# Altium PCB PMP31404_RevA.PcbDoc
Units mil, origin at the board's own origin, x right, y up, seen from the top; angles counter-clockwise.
Board outline 1387.8 x 708.66 mil, 4 copper layers (Top Layer, Layer 1, Layer 2, Bottom Layer), stack 78.58 mil thick; 42 components, 29 nets, 108 pads, 48 vias.
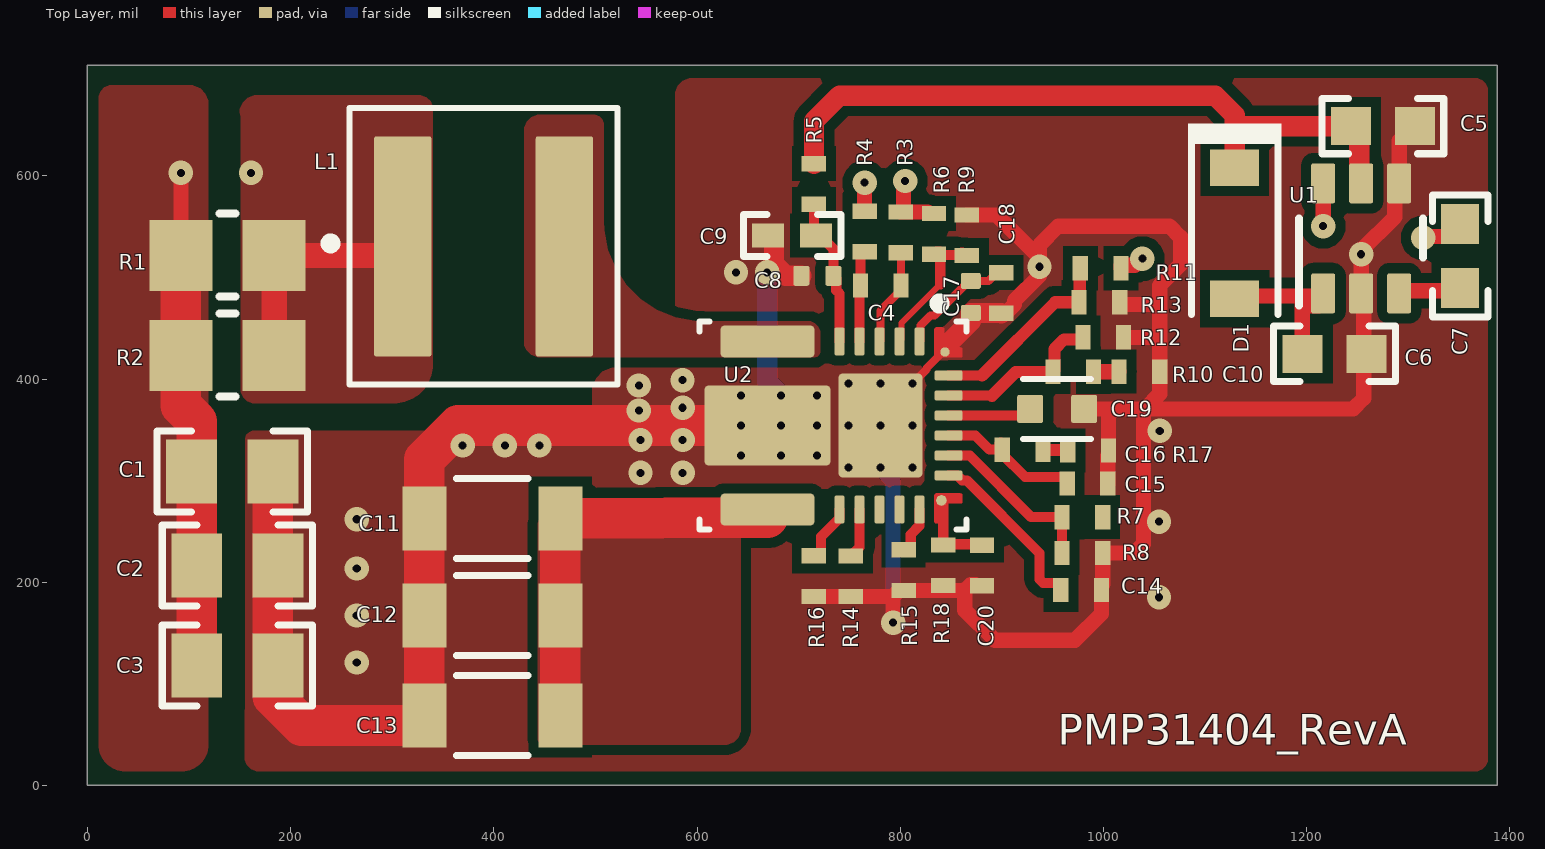
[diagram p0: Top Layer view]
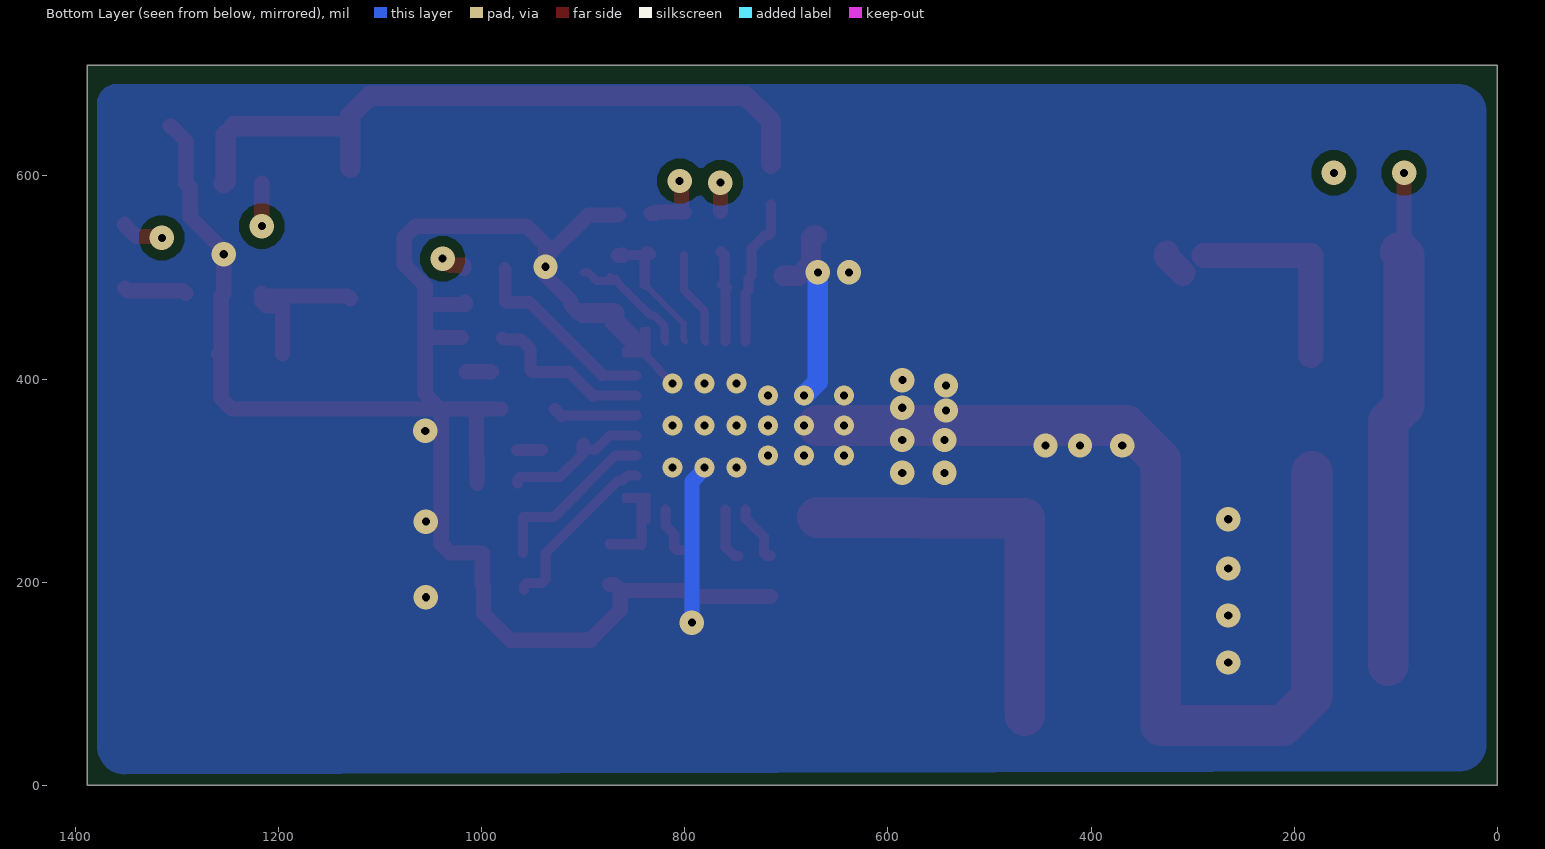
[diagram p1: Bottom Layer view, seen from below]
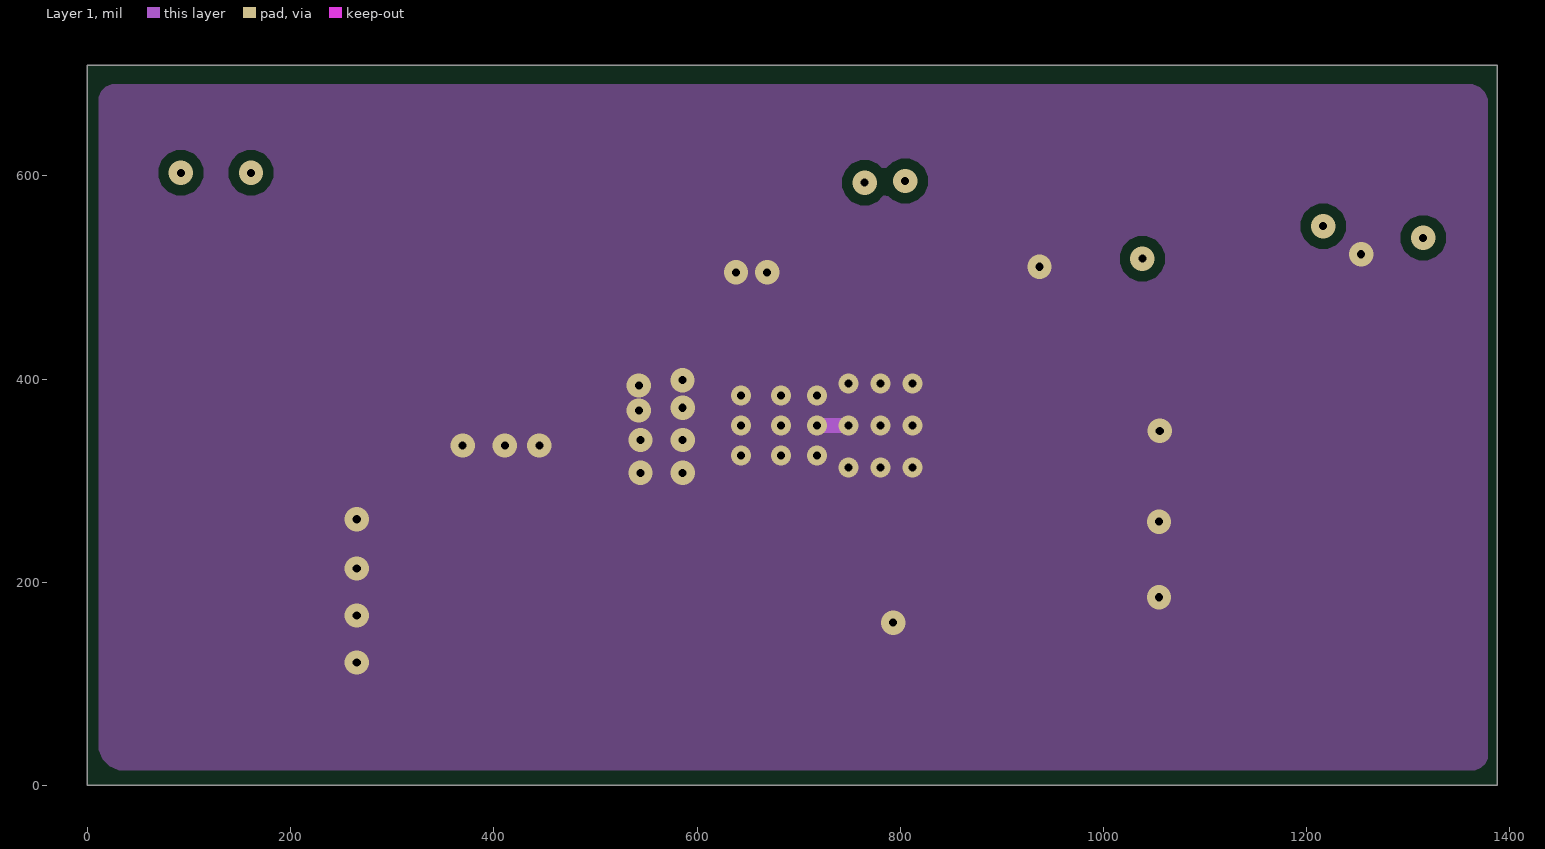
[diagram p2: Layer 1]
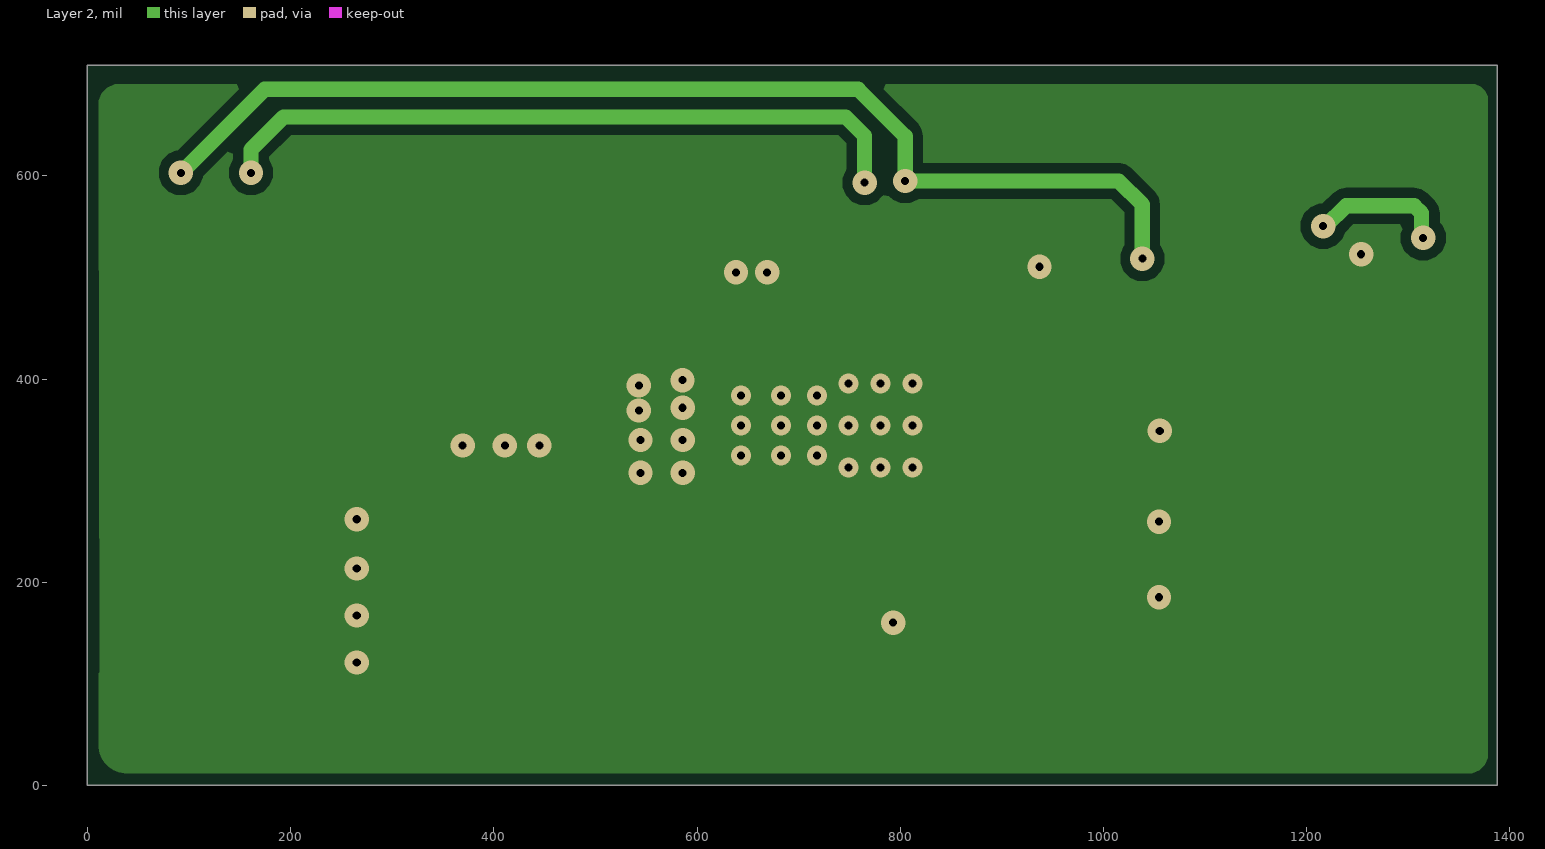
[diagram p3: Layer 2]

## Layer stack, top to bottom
Top Solder: solder mask 0.4, Solder Resist, Dk 3.5
Top Layer: signal copper 4.1339
Dielectric 1: prepreg 2.8, PP-006, Dk 4.1
Layer 1: signal copper 2.756
Dielectric1: core 59.2, FR-4 High Tg, Dk 4.8
Layer 2: signal copper 2.756
Dielectric 2: prepreg 2.8, PP-006, Dk 4.1
Bottom Layer: signal copper 4.1339
Bottom Solder: solder mask 0.4, Solder Resist, Dk 3.5

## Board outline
0,0 0,708.66 1387.8,708.66 1387.8,0

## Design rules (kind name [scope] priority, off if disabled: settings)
AcuteAngle [All] p1: minimum=4.50000000000000E+0001 checktracksonly=FALSE
AssemblyTestPointUsage [All] p1: valid=2
BoardOutlineClearance BoardOutlineClearance_MountingHoles [OnCopper and InComponentClass('Mounting Holes')] p1: gap=1 ignorepadtopadclearanceinfootprint=FALSE
BoardOutlineClearance BoardOutlineClearance_Poly [OnCopper and IsPoly] p2: gap=1 ignorepadtopadclearanceinfootprint=FALSE
BoardOutlineClearance [OnCopper and Not InComponentClass('Logo') and not InComponentClass('FiducialMark') and not InRegion(1000,500,4000,800) and not InPoly] p3: gap=1 ignorepadtopadclearanceinfootprint=FALSE
Clearance Clearance_Keepouts [((IsTrack Or IsArc) And Not InPoly) And IsFree and IsKeepOut vs ((IsTrack Or IsArc) And Not InPoly) And IsFree and IsKeepOut] p1: gap=0 ignorepadtopadclearanceinfootprint=FALSE
Clearance Clearance_Poly [InPolygon] p2: gap=10 ignorepadtopadclearanceinfootprint=TRUE
Clearance Clearance_FiducialMark [IsKeepOut and InComponentClass('FiducialMark') vs IsPad and InComponentClass('FiducialMark')] p3: gap=0 ignorepadtopadclearanceinfootprint=FALSE
Clearance [All] p4: gap=4 ignorepadtopadclearanceinfootprint=TRUE
ComponentClearance ComponentClearance_MountingHoles_FiducialMarks [InComponentClass('Mounting Holes') vs InComponentClass('FiducialMark')] p1: gap=50 collisioncheckmode=3 verticalgap=10 showdistances=FALSE
ComponentClearance ComponentClearance_Shunt [InComponentClass('Header') vs InComponentClass('Shunt')] p2: gap=0 collisioncheckmode=3 verticalgap=0 showdistances=FALSE
ComponentClearance ComponentClearance_Logo [InComponentClass('Logo')] p3: gap=30 collisioncheckmode=3 verticalgap=10 showdistances=FALSE
ComponentClearance ComponentClearance_ScrewToNut [(HasFootprint('NY PMS 440 0025 PH')) vs (HasFootprint('Keystone_1902C'))] p4: gap=5 collisioncheckmode=3 verticalgap=10 showdistances=FALSE
ComponentClearance ComponentClearance_MountingHoles [InComponentClass('Mounting Holes')] p5: gap=100 collisioncheckmode=3 verticalgap=100000 showdistances=FALSE
ComponentClearance ComponentClearance_SmallPassives [HasFootprint('0201*') or HasFootprint('0402*') or HasFootprint('0508') or HasFootprint('0603*') or HasFootprint('0612') or HasFootprint('0805*') or HasFootprint('0815*') or HasFootprint('0830*') or HasFootprint('1206*') or HasFootprint('1210*') or HasFootprint('1808*') or HasFootprint('1812*') or HasFootprint('1825*') or HasFootprint('2010*') or HasFootprint('2220*') or HasFootprint('2225*') or HasFootprint('2512*') or HasFootprint('2728*') or HasFootprint('3518*') vs HasFootprint('0201*') or HasFootprint('0402*') or HasFootprint('0508') or HasFootprint('0603*') or HasFootprint('0612') or HasFootprint('0805*') or HasFootprint('0815*') or HasFootprint('0830*') or HasFootprint('1206*') or HasFootprint('1210*') or HasFootprint('1808*') or HasFootprint('1812*') or HasFootprint('1825*') or HasFootprint('2010*') or HasFootprint('2220*') or HasFootprint('2225*') or HasFootprint('2512*') or HasFootprint('2728*') or HasFootprint('3518*')] p6: gap=5 collisioncheckmode=3 verticalgap=5 showdistances=FALSE
ComponentClearance ComponentClearance_THtoSMT [IsThruComponent vs IsSMTComponent] p7: gap=30 collisioncheckmode=3 verticalgap=30 showdistances=FALSE
ComponentClearance ComponentClearance_THtoTH [IsThruComponent vs IsThruComponent] p8: gap=20 collisioncheckmode=3 verticalgap=30 showdistances=FALSE
ComponentClearance [All] p9: gap=5 collisioncheckmode=3 verticalgap=5 showdistances=FALSE
DiffPairsRouting [All] p1: maxlimit=100 minlimit=10 mostfreqgap=10 toplayer_minwidth=15 toplayer_maxwidth=15 toplayer_prefwidth=15 midlayer1_minwidth=15 midlayer1_maxwidth=15 midlayer1_prefwidth=15 midlayer2_minwidth=15 midlayer2_maxwidth=15 midlayer2_prefwidth=15 bottomlayer_minwidth=15 bottomlayer_maxwidth=15 bottomlayer_prefwidth=15 maxuncoupledlength=1000
FabricationTestPointUsage TestPointUsage [All] p1: valid=2 allowmultiple=FALSE
FabricationTestpoint Testpoint [All] p1: side=3 testpointundercomponent=TRUE minsize=40 maxsize=100 preferedsize=60 minholesize=0 maxholesize=40 preferedholesize=32 testpointgrid=1 allowsidetop=TRUE allowsidebottom=TRUE usegrid=TRUE gridtolerance=0.01
FanoutControl Fanout_LCC [IsLCC] p1: bgadir=Out bgaviamode=Centered fanoutstyle=Auto fanoutdirection=Alternating viagrid=1 // Fanout_LCC (Default Rule)
FanoutControl Fanout_BGA [IsBGA] p2: bgadir=Out bgaviamode=Centered fanoutstyle=Auto fanoutdirection=Alternating viagrid=1 // Fanout_BGA (Default Rule)
FanoutControl Fanout_Default [All] p4: bgadir=Out bgaviamode=Centered fanoutstyle=Auto fanoutdirection=Alternating viagrid=1 // Fanout_Default (Default Rule)
FanoutControl Fanout_Small [(CompPinCount < 5)] p5: bgadir=Out bgaviamode=Centered fanoutstyle=Auto fanoutdirection=OutThenIn viagrid=1 // Fanout_Small (Default Rule)
HoleSize [All] p1: absolutevalues=TRUE maxlimit=251 minlimit=7.87 maxpercent=80.000 minpercent=20.000
MinimumAnnularRing MinimumAnnularRing_ThermalPadVias [IsVia and InAnyComponent] p1: minimumring=5.91
MinimumAnnularRing [All] p2: minimumring=7.87
MinimumSolderMaskSliver MinimumSolderMaskSliver_Logo [InComponentClass('Logo') vs InComponentClass('Logo')] p1: minsoldermaskwidth=0.7
MinimumSolderMaskSliver [All] p2: minsoldermaskwidth=3.94
PlaneConnect [All] p1: planeconnectstyle=Relief reliefexpansion=10 reliefentries=4 reliefconductorwidth=10 reliefairgap=10
PolygonConnect [All] p1: connectstyle=Direct reliefconductorwidth=10 reliefentries=4 polygonreliefangle="90 Angle" airgapwidth=10
RoutingVias ThermalPadVias [IsVia and InAnyComponent] p1: holewidth=7.87 width=19.68 viastyle="Through Hole" minholewidth=7.87 minwidth=19.68 maxholewidth=12.99 maxwidth=23.62
RoutingVias [All] p2: holewidth=16 width=34 viastyle="Through Hole" minholewidth=7.87 minwidth=24 maxholewidth=40 maxwidth=65
SilkToBoardRegionClearance [Not ((IsComment or IsDesignator) And (Hide <> 'False')) and not InRegion(1000,500,4000,800)] p1:
SilkToSilkClearance SilkToSilkClearance_Pb-FreeLogo [(HasFootprint('Pb-Free_Overlay_Medium') OR HasFootprint('Pb-Free_Overlay_Small')) vs (HasFootprint('Pb-Free_Overlay_Medium') OR HasFootprint('Pb-Free_Overlay_Small'))] p1: silktosilkclearance=0
SilkToSilkClearance [All] p2: silktosilkclearance=0
SilkToSolderMaskClearance SilkToComponentPadClearance [(IsPad or IsFill or IsRegion) and InAnycomponent] p1: minsilkscreentomaskgap=0 clearancetoexposedcopper=TRUE
SilkToSolderMaskClearance "Silk to Solder Mask Opening" [All] p2: minsilkscreentomaskgap=3.94 clearancetoexposedcopper=FALSE
SolderMaskExpansion [All] p1: expansion=1.97 istentingtop=FALSE
UnRoutedNet [All] p1: checkbadconnections=TRUE
Width [All] p1: maxlimit=100 minlimit=6 preferedwidth=10 checkconnectedcopper=TRUE
14 further rules are at their usual default settings.

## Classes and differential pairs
component class PMP31404_RevA: C1 C2 C3 C4 C5 C6 C7 C9 C10 C12 C14 C16 C18 D1 L1 R1 R2 R3 R4 R5 R6 R7 R8 R9 R10 R11 R12 R13 R14 R15 R16 R17 R18 U1 U2

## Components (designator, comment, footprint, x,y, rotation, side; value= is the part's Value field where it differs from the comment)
C1 "GCM21BR71A106KE22L" 0805_HV 142.52,309.06 r0 top value=10uF
C2 "GCM21BR71A106KE22L" 0805_HV 147.64,216.54 r0 top value=10uF
C3 "GCM21BR71A106KE22L" 0805_HV 147.64,118.11 r0 top value=10uF
C4 "CGA2B2C0G1H101J050BA" 0402S 780.78,492.13 r0 top value=100pF
C5 "EMK107BB7225MA-T" 0603 1274.99,648.94 r0 top value=2.2uF
C6 "GRM188R71A225KE15J" 0603 1227.26,424.8 r0 top value=2.2uF
C7 "GRM188R71A225KE15J" 0603 1351.15,521.07 r270 top value=2.2uF
C8 "GRM155R62A104ME14D" FP-GRM155R62A104ME14D_0402-S 718.41,501.67 r180 top value=100nF
C9 "CC0402MRX5R6BB105" 0402 693.57,541.29 r0 top value=1uF
C10 "" 0402S 1035.35,407.33 r0 top value=TBD
C11 "CL31B106KBHNNNE" 1206_180 398.43,262.76 r180 top value=10uF
C12 "CL31B106KBHNNNE" 1206_180 398.43,167.32 r180 top value=10uF
C13 "CL31B106KBHNNNE" 1206_180 398.43,68.9 r180 top value=10uF
C14 "GRM155R61A334KE15D" 0402S 977.99,192.34 r0 top value=0.33uF
C15 "GRM1555C1H680JA01D" 0402S 984.32,297.26 r0 top value=68pF
C16 "GRM155R71H682KA88D" 0402S 920.47,330.58 r0 top value=6800pF
C17 "GRM155R62A104ME14D" FP-GRM155R62A104ME14D_0402-S 869.44,480.84 r90 top value=100nF
C18 "GRM155R60J475ME87D" 0402_065S 899.33,484.73 r270 top value=4.7uF
C19 "GRT188R71C334KE01D" FP-GRT188R71C334KE01D_0603-MFG 954.43,370.65 r180 top value=330nF
C20 "GRM1555C1H470JA01D" 0402S 880.48,216.53 r270 top value=47pF
D1 "MBR0520LT1G" SOD-123 1129.11,543.57 r270 top value=20V
L1 "XGL6060-152MEC" FP-XGL6060-152MEC_SMT_IND_6MM51_6MM71-MFG 389.83,530.55 r0 top value=1.5uH
R1 "WSLP12061L000FEA" WSLP1206-001 137.8,521.65 r0 top value=DNP
R2 "WSLP12061L000FEA" WSLP1206-001 137.8,423.23 r0 top value=0.001
R3 "ERJ-2RKF1000X" 0402S 800.35,544.34 r90 top value=100
R4 "ERJ-2RKF1000X" 0402S 764.86,545.25 r90 top value=100
R5 "CRCW040210K5FKED" 0402S 715,592 r90 top value=0
R6 "CRCW040290K9FKED" 0402S 833.14,542.86 r90 top value=90.9k
R7 "CRCW040210K5FKED" 0402S 979.19,264.14 r180 top value=0
R8 "CRCW040280K6FKED" 0402S 979.23,228.77 r180 top value=80.6k
R9 "CRCW040247K5FKED" 0402S 865.35,541.59 r270 top value=47.5k
R10 "CRCW040212K1FKED" 0402S 970.2,407.08 r180 top value=12.1k
R11 "CRCW040210K0FKED" 0402S 997.26,509.11 r0 top value=10.0k
R12 "CRCW040288K7FKED" 0402S 999.83,441.01 r180 top value=88.7k
R13 "DNP" 0402S 996.01,475.61 r180 top
R14 "CRCW040210K5FKED" 0402S 751.38,205.96 r90 top value=10.5k
R15 "CRCW040290K9FKED" 0402S 803.26,211.92 r270 top value=90.9k
R16 "CRCW040210K5FKED" 0402S 714.98,206.07 r90 top value=0
R17 "CRCW040215K0FKED" 0402S 984.91,329.67 r180 top value=15.0k
R18 "CRCW040252K3FKED" 0402S 842.36,216.78 r90 top value=52.3k
U1 "LM2665M6" DBV0006A_N 1253.65,538.49 r90 top
U2 "XLMG5126VBTT" VBT0022A-MFG 735.24,354.33 r270 top

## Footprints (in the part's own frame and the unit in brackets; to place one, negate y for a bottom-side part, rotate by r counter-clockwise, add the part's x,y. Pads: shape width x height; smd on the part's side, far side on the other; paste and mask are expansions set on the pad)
0402 [mm] "0402 from SM-752 data"
  rect 0.8x0.6 smd: 1(-0.6,0) 2(0.6,0)
  silkscreen extent -1.22,-0.52 1.22,0.52, body extent -0.55,-0.3 0.55,0.3, height 0.6
0402_065S [mil] "Based on C0402S footprint from PADS legacy"
  rect 15x24 smd: 1(-20,0) 2(20,0)
  body extent -22,-12 22,12, height 26
0402S [mil] "Based on C0402S footprint from PADS legacy"
  rect 15x24 smd: 1(-20,0) 2(20,0)
  body extent -22,-12 22,12, height 24
0603 [mm] "0603 from SM-752 data"
  rect 1x0.95 smd: 1(-0.8,0) 2(0.8,0)
  silkscreen extent -1.52,-0.69 1.52,0.69, body extent -0.87,-0.47 0.87,0.47, height 1
0805_HV [mil] "0805 with 30mil clearance between pads"
  rect 50x63 smd: 1(-40,0) 2(40,0)
  silkscreen extent -74,-40 74,40, body extent -43,-29 43,29, height 57
1206_180 [mm] "1206_180"
  rect 1.1x1.6 smd: 1(-1.7,0) 2(1.7,0)
  silkscreen extent -0.9,-1 0.9,1, body extent -1.75,-0.95 1.75,0.95, height 1.8
DBV0006A_N [mm] "SOT23, 6-Leads, Body 2.9x1.6mm, Pitch 0.95mm, Lead Span 2.8mm, IPC Medium Density"
  rrect17% 1x0.6 smd: 1(-1.375,0.95) 2(-1.375,0) 3(-1.375,-0.95) 4(1.375,-0.95) 5(1.375,0) 6(1.375,0.95)
  silkscreen extent -1.68,-1.55 0.5,1.55, body extent -1.42,-1.46 1.42,1.46, height 1.12
FP-GRM155R62A104ME14D_0402-S [mm]
  rrect25% 0.4x0.5 smd paste+0 mask+0: 1(-0.4,0) 2(0.4,0)
  body extent -0.7,-0.37 0.7,0.38, height 0.25
FP-GRT188R71C334KE01D_0603-MFG [mm]
  rrect15% 0.65x0.7 smd paste+0 mask+0: 1(-0.675,0) 2(0.675,0)
  silkscreen extent -0.85,-0.75 0.85,0.75, body extent -1.1,-0.55 1.1,0.55, height 0.25
FP-XGL6060-152MEC_SMT_IND_6MM51_6MM71-MFG [mm]
  rrect7% 1.43x5.5 smd paste+0 mask+0: 1(-2.02,0) 2(2.02,0)
  silkscreen extent -3.95,-3.45 3.35,3.45, body extent -3.45,-3.55 3.45,3.55, height 0.25
SOD-123 [mm] "On Semi recommended land pattern"
  rect 0.915x1.22 smd: 1(-1.637,0) 2(1.637,0)
  silkscreen extent -2.74,-1.17 2.03,1.17, body extent -1.93,-0.9 1.93,0.9, height 1.35
VBT0022A-MFG [mm] "Recommended Land Pattern"
  round 0.234 smd paste+0 mask+0: 1(-1.837,2.762)
  rrect40% 0.7x0.25 smd paste+0 mask+0: 2(-2.1,2.125) 3(-2.1,1.625) 4(-2.1,1.125) 5(-2.1,0.625) 6(-2.1,0.125) 10(2.1,0.125) 11(2.1,0.625) 12(2.1,1.125) 13(2.1,1.625) 14(2.1,2.125)
  rrect25% 0.8x2.35 smd paste-1000 mask-1000: 7(-2.1,-1.675) 9(2.1,-1.675)
  rrect10% 2x3.15 smd paste-1000 mask-1000: 8(0,-1.675)
  round 0.265 smd paste+0 mask+0: 15(1.875,2.675)
  rrect40% 0.25x0.7 smd paste+0 mask+0: 16(1.25,2.85) 17(0.75,2.85) 18(0.25,2.85) 19(-0.25,2.85) 20(-0.75,2.85) 21(-1.25,2.85)
  rrect10% 2.6x2.1 smd paste-1000 mask-1000: 22(0,1.15)
  Top Layer region: -2.4,2.5 -2.419,2.504 -2.435,2.515 -2.446,2.531 -2.45,2.55 -2.45,2.55 -2.45,2.7 -2.443,2.725 -2.425,2.743 -2.4,2.75 -2.4,2.75 -2.05,2.75 -2.012,2.758 -1.979,2.779 -1.958,2.812 -1.95,2.85 -1.95,2.85 -1.95,3.15 -1.943,3.175 -1.925,3.193 -1.9,3.2 -1.9,3.2 -1.75,3.2 -1.725,3.193 -1.707,3.175 -1.7,3.15 -1.7,3.15 -1.7,2.55 -1.704,2.531 -1.715,2.515 -1.731,2.504 -1.75,2.5 -1.75,2.5
  Top Layer region: 2.4,2.5 2.419,2.504 2.435,2.515 2.446,2.531 2.45,2.55 2.45,2.55 2.45,2.7 2.446,2.719 2.435,2.735 2.419,2.746 2.4,2.75 2.4,2.75 2.05,2.75 2.012,2.758 1.979,2.779 1.958,2.812 1.95,2.85 1.95,2.85 1.95,3.15 1.946,3.169 1.935,3.185 1.919,3.196 1.9,3.2 1.9,3.2 1.75,3.2 1.725,3.193 1.707,3.175 1.7,3.15 1.7,3.15 1.7,2.55 1.704,2.531 1.715,2.515 1.731,2.504 1.75,2.5 1.75,2.5
  silkscreen extent -3.17,-3.37 2.6,3.3, body extent -2.25,-3 2.25,3, height 0.85
WSLP1206-001 [mm] "Vishay"
  rect 1.57x1.78 smd: 1(-1.165,0) 2(1.165,0)
  silkscreen extent -0.2,-1.02 0.2,1.05, body extent -1.73,-0.93 1.73,0.93, height 0.89

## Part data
C1 C2 C3: library part CMP-0008017-1, "CAP, CERM, 10 uF, 10 V, +/- 10%, X7R, 0805", Cap_Case=0805, Manufacturer=MuRata, Supplier Part Number 1=490-10674-1-ND, TempCo=X7R, Tolerance_%=10%, Value1=Unknown, Value2=10V, ValueDisplayed=10uF
C4: library part CMP-0006308-2, "CAP, CERM, 100 pF, 50 V, +/- 5%, C0G/NP0, AEC-Q200 Grade 1, 0402", Cap_Case=0402, Manufacturer=TDK, Supplier Part Number 1=445-5596-1-ND, TempCo=C0G/NP0, Tolerance_%=5%, Value1=Unknown, Value2=50V, ValueDisplayed=100pF
C5: library part CMP-0064934-2, "CAP, CERM, 2.2 uF, 16 V,+/- 10%, X7R, 0603", Cap_Case=0603, Manufacturer="Taiyo Yuden", Supplier Part Number 1=587-4864-1-ND, TempCo=X7R, Tolerance_%=10%, Value1=Unknown, Value2=16V, ValueDisplayed=2.2uF
C6 C7: library part CMP-0084284-1, "CAP, CERM, 2.2 µF, 10 V,+/- 10%, X7R, AEC-Q200 Grade 1, 0603", Cap_Case=0603, Manufacturer=MuRata, TempCo=X7R, Tolerance_%=10%, Value2=10V, ValueDisplayed=2.2µF
C8 C17: library part CMP-0093748-2, "Chip Multilayer Ceramic Capacitors for General Purpose, 0402, 0.10uF, X5R, 15%, 20%, 100V", Manufacturer=Murata, Operating Temperature Range="-55°C to +85°C", TempCo=15%, Temperature Characteristic=X5R, Tolerance_%=20%, ValueDisplayed=0.10uF
C9: library part CMP-0081457-1, "CAP, CERM, 1 µF, 10 V,+/- 20%, X5R, 0402", Cap_Case=0402, Manufacturer="Yageo America", TempCo=X5R, Tolerance_%=20%, Value2=10V, ValueDisplayed=1µF
C10: library part CMP-0006468-2, "CAP, CERM, TBD", Cap_Case=0402, Manufacturer=MuRata, PartNumber=TBD, Supplier Part Number 1=81-GRM1555C1H470JA1D, TempCo=C0G/NP0, Tolerance_%=5%, Value1=Unknown, Value2=50V
C11 C12 C13: library part CMP-0008802-2, "CAP, CERM, 10 uF, 50 V, +/- 10%, X7R, 1206", Cap_Case=1206, Manufacturer=Samsung, Supplier Part Number 1=1276-6767-1-ND, TempCo=X7R, Tolerance_%=10%, Value1=Unknown, Value2=50V, ValueDisplayed=10uF
C14: library part CMP-0006575-1, "CAP, CERM, 0.33 uF, 10 V, +/- 10%, X5R, 0402", Cap_Case=0402, Manufacturer=MuRata, Supplier Part Number 1=490-3263-1-ND, TempCo=X5R, Tolerance_%=10%, Value1=Unknown, Value2=10V, ValueDisplayed=0.33uF
C15: library part CMP-0006485-2, "CAP, CERM, 68 pF, 50 V, +/- 5%, C0G/NP0, 0402", Cap_Case=0402, Manufacturer=MuRata, Supplier Part Number 1=81-GRM1555C1H680JA1D, TempCo=C0G/NP0, Tolerance_%=5%, Value1=Unknown, Value2=50V, ValueDisplayed=68pF
C16: library part CMP-0006696-2, "CAP, CERM, 6800 pF, 50 V, +/- 10%, X7R, 0402", Cap_Case=0402, Manufacturer=MuRata, Supplier Part Number 1=490-4515-1-ND, TempCo=X7R, Tolerance_%=10%, Value1=Unknown, Value2=50V, ValueDisplayed=6800pF
C18: library part CMP-0006553-3, "CAP, CERM, 4.7 uF, 6.3 V, +/- 20%, X5R, 0402", Cap_Case=0402, Manufacturer=MuRata, Supplier Part Number 1=490-5408-1-ND, TempCo=X5R, Tolerance_%=20%, Value1="0.009 ohm", Value2=6.3V, ValueDisplayed=4.7uF
C19: library part CMP-0121474-1, "Multi-Layer Ceramic Capacitor 330nF 16V X7R ±10% 0603 Paper T/R", Manufacturer=Murata, Operating Temperature Range="-55°C to +125°C", TempCo=15%, Temperature Characteristic=X7R, Tolerance_%=10%, ValueDisplayed=330nF
C20: library part CMP-0006468-2, "CAP, CERM, 47 pF, 50 V, +/- 5%, C0G/NP0, 0402", Cap_Case=0402, Manufacturer=MuRata, Supplier Part Number 1=81-GRM1555C1H470JA1D, TempCo=C0G/NP0, Tolerance_%=5%, Value1=Unknown, Value2=50V, ValueDisplayed=47pF
D1: library part CMP-0028524-1, "Diode, Schottky, 20 V, 0.5 A, SOD-123", Manufacturer="ON Semiconductor", Supplier Part Number 1=MBR0520LT1GOSCT-ND, Value1=0.5A, Value2=0.385V
L1: library part CMP-0121324-1, "1.5 µH Shielded Molded Inductor 20.2 A 3.8mOhm Max Nonstandard", Digikey Part Number=2457-XGL6060-152MEC-ND, Manufacturer=Coilcraft, Operating Temperature Range=to, Self Resonant Frequency=41MHz, Test Frequency=1MHz, Tolerance_%=20%
R1: library part CMP-0018569-2, "DNP", Manufacturer=Vishay-Dale, Power_W=1W, Supplier Part Number 1=54X6165, TempCo="275 ppm/C", Tolerance_%=1%, Value_Code=1L000
R2: library part CMP-0018569-2, "RES, 0.001, 1%, 1 W, 1206", Manufacturer=Vishay-Dale, Power_W=1W, Supplier Part Number 1=54X6165, TempCo="275 ppm/C", Tolerance_%=1%, Value_Code=1L000, ValueDisplayed=0.001
R3 R4: library part CMP-0026656-1, "RES, 100, 1%, 0.1 W, 0402", Manufacturer=Panasonic, Power_W=100mW, Supplier Part Number 1=P100LCT-ND, TempCo="100 ppm/C", Tolerance_%=1%, Value2=0.1W, Value_Code=100R, ValueDisplayed=100
R5 R7 R16: library part CMP-0025960-2, "RES,", Manufacturer=Vishay-Dale, Power_W=63mW, Supplier Part Number 1=541-10.5KLCT-ND, TempCo="100 ppm/C", Tolerance_%=1%, Value2=0.063W, Value_Code=10k5, ValueDisplayed=0
R6 R15: library part CMP-0026605-1, "RES, 90.9 k, 1%, 0.063 W, 0402", Manufacturer=Vishay-Dale, Power_W=63mW, Supplier Part Number 1=541-90.9KLCT-ND, TempCo="100 ppm/C", Tolerance_%=1%, Value2=0.063W, Value_Code=90k9, ValueDisplayed=90.9k
R8: library part CMP-0026570-2, "RES, 80.6 k, 1%, 0.063 W, AEC-Q200 Grade 0, 0402", Manufacturer=Vishay-Dale, Power_W=63mW, Supplier Part Number 1=541-80.6KLCT-ND, TempCo="100 ppm/C", Tolerance_%=1%, Value2=0.063W, Value_Code=80k6, ValueDisplayed=80.6k
R9: library part CMP-0026395-2, "RES, 47.5 k, 1%, 0.063 W, AEC-Q200 Grade 0, 0402", Manufacturer=Vishay-Dale, Power_W=63mW, Supplier Part Number 1=541-47.5KLCT-ND, TempCo="100 ppm/C", Tolerance_%=1%, Value2=0.063W, Value_Code=47k5, ValueDisplayed=47.5k
R10: library part CMP-0025991-2, "RES, 12.1 k, 1%, 0.063 W, 0402", Manufacturer=Vishay-Dale, Power_W=63mW, Supplier Part Number 1=541-12.1KLCT-ND, TempCo="100 ppm/C", Tolerance_%=1%, Value2=0.063W, Value_Code=12k1, ValueDisplayed=12.1k
R11: library part CMP-0025958-2, "RES, 10.0 k, 1%, 0.063 W, 0402", Manufacturer=Vishay-Dale, Power_W=63mW, Supplier Part Number 1=541-10.0KLCT-ND, TempCo="100 ppm/C", Tolerance_%=1%, Value2=0.063W, Value_Code=10k0, ValueDisplayed=10.0k
R12: library part CMP-0026586-2, "RES, 88.7 k, 1%, 0.063 W, AEC-Q200 Grade 0, 0402", Manufacturer=Vishay-Dale, Power_W=63mW, Supplier Part Number 1=541-88.7KLCT-ND, TempCo="100 ppm/C", Tolerance_%=1%, Value2=0.063W, Value_Code=88k7, ValueDisplayed=88.7k
R13: library part CMP-0025960-2, "RES,", Manufacturer=Vishay-Dale, Power_W=63mW, Supplier Part Number 1=541-10.5KLCT-ND, TempCo="100 ppm/C", Tolerance_%=1%, Value2=0.063W, Value_Code=10k5
R14: library part CMP-0025960-2, "RES, 10.5 k, 1%, 0.063 W, 0402", Manufacturer=Vishay-Dale, Power_W=63mW, Supplier Part Number 1=541-10.5KLCT-ND, TempCo="100 ppm/C", Tolerance_%=1%, Value2=0.063W, Value_Code=10k5, ValueDisplayed=10.5k
R17: library part CMP-0026027-3, "RES, 15.0 k, 1%, 0.063 W, AEC-Q200 Grade 0, 0402", Manufacturer=Vishay-Dale, Power_W=63mW, Supplier Part Number 1=541-15.0KLCT-ND, TempCo="100 ppm/C", Tolerance_%=1%, Value2=0.063W, Value_Code=15k0, ValueDisplayed=15.0k
R18: library part CMP-0026441-1, "RES, 52.3 k, 1%, 0.063 W, 0402", Manufacturer=Vishay-Dale, Power_W=63mW, Supplier Part Number 1=541-52.3KLCT-ND, TempCo="100 ppm/C", Tolerance_%=1%, Value2=0.063W, Value_Code=52k3, ValueDisplayed=52.3k
U1: library part CMP-0072134-1, "Switched Capacitor Voltage Converter, 6-pin SOT-23", Manufacturer="Texas Instruments", PackageTopMarking=S04A*XTT, PowerWise=N
U2: library part CMP-0125772-1, "2.5MHz 42V wide-VIN synchronous GaN boost converter with output voltage tracking 22-VQFN-FCRLF -40 to 125", Manufacturer="Texas Instruments", Max Supply Voltage=42V, Min Supply Voltage=2.5V, Operating Temperature Range="-40°C to +125°C", Output Voltage=6-60V, Switching Frequency=300-2500kHz

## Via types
v1: diameter 24, hole 8, Top Layer to Bottom Layer, tented both sides, 21 vias
v2: diameter 19.68, hole 7.87, Top Layer to Bottom Layer, tented both sides, 18 vias
v3: diameter 24, hole 7.87, Top Layer to Bottom Layer, tented both sides, 9 vias

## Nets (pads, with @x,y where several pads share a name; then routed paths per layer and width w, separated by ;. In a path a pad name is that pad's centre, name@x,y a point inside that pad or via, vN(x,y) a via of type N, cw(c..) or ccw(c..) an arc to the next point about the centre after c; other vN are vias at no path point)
"5V input": C6.1 D1.2 U1.1 | length 169.4
  Top Layer w15: D1.2 1131.73,481.73 1192.62,481.73 ; C6.1 1195.77,478.59 ccw(c1192.62,478.59) 1192.62,481.73 ; U1.1@1204.55,472.17 1211.93,472.17 1216.24,476.48 U1.1 1213.62,481.73 1192.62,481.73
"AT RK EXT": R7.1
ATRK: R7.2 R8.2 U2.17 | length 172.3
  Top Layer w10: U2.17 847.52,324.72 868.33,324.72 928.91,264.14 R7.2 ; R8.2 R7.2
BIAS: C8.1 C9.2 R5.1 U2.6 | length 147.7
  Top Layer w10: R5.1 715,543.48 C9.2 721.13,541.29 734.16,528.26 C8.1 737.03,498.79 737.03,487.48 740.16,484.35 U2.6
CFG1: R14.2 U2.11 | length 53.7
  Top Layer w10: R14.2@746.88,225.96 R14.2 759.84,234.42 U2.11
CFG2: R16.2 U2.10 | length 58.6
  Top Layer w10: R16.2 719.48,226.07 721.98,228.57 721.98,244.78 740.16,262.95 U2.10
COMP: C15.1 C16.1 U2.18 | length 148
  Top Layer w10: U2.18 873.84,344.49 887.75,330.58 C16.1 900.47,326.08 922.82,303.72 961.82,303.72 964.32,301.22 C15.1
  Top Layer w12: C16.1@898.97,336.58 900.47,335.08 C16.1
CSA: C4.2 R3.1 U2.4 | length 97.1
  Top Layer w8: U2.4 780.45,437.93 780.45,467.3 800.78,487.63 C4.2 ; C4.2@800.78,489.05 R3.1@800.78,522.21
CSB: C4.1 R4.1 U2.5 | length 96.7
  Top Layer w10: C4.1@758.28,489.63 C4.1 760.78,522.75 763.28,525.25 R4.1 ; U2.5 759.92,437.09 759.92,489.63 C4.1@763.28,492.98
DLY: C14.1 U2.16 | length 174.9
  Top Layer w10: U2.16 856.14,305.12 860.98,300.28 865.4,300.28 937,228.68 937,203 940.66,199.34 955.49,199.34 957.99,196.84 C14.1
GND: C1.2 C2.2 C3.2 C5.2 C6.2 C8.2 C9.1 C10.2 C11.2 C12.2 C13.2 C14.2 C15.2 C17.1 C18.2 C19.1 C20.2 R8.1 R9.1 R12.1 R13.1 R14.1 R15.2 R16.1 R17.1 R18.1 U1.2 U1.4 U2.1 U2.8 U2.22 | length 3348.3
  Top Layer w6: U2.1 U2.1@844.86,426.67
  Top Layer w8: v2(812.01,395.67) v2(812.01,395.67) 825.66,409.4 825.66,410.63 841.48,426.44 843.77,426.44 U2.1
  Top Layer w15: R16.1 R15.2@792.9,186.07 ; v3(792.9,160.19) R15.2@792.9,186.07 ; R9.1 894.83,561.59 v1@937,519.42 ; C20.2@873.93,197.93 869.43,197.93 863.42,191.92 ; C18.2 903.83,464.73 912.5,473.4 912.5,477.17 937,501.67 v1@937,519.42 ; C19.1 1010.82,370.65 ; C15.2 1004.32,324.58 1004.91,325.17 R17.1 1004.91,364.73 1010.82,370.65 ; R13.1 1016.01,473.4 1055.35,473.4 ; R12.1 1054.7,441.01 1055.35,440.37 ; C6.2 C6.2@1256.2,427.35 ; C5.2 1305.5,648.94 1291.05,634.48 U1.4 1286.74,588.31 1286.74,559.63 1253.65,526.54 U1.2 1256.2,481.8 C6.2@1256.2,427.35 ; R15.2@792.9,186.07 798.76,191.92 R15.2 863.42,191.92 ; 863.42,191.92 863.42,172.58 893,143 972,143 997.99,168.99 C14.2 997.99,196.84 999.23,198.09 R8.1 1030.71,228.77 1039.5,237.55 1039.5,369.5 1040.64,370.65 ; v1@937,519.42 937,532.02 955.49,550.5 1065,550.5 1076,539.5 1076,512.67 1055.35,492.01 1055.35,473.4 ; 1010.82,370.65 1040.64,370.65 ; 1040.64,370.65 1245.73,370.65 1256.2,381.11 C6.2@1256.2,427.35 ; 1040.64,370.65 1055.35,385.35 C10.2 1055.35,440.37 ; 1055.35,440.37 1055.35,473.4
  Top Layer w20: v3(669,505) 669,506.08 675.69,512.78 v3@675.69,513.38 ; C9.1 673.88,541.29 675.69,539.48 v3@675.69,513.38 ; C8.2 687.41,501.67 v3@675.69,513.38 ; 844.71,432.31 869.43,457.03 C17.1 898.96,465.09 C18.2
  Top Layer w40: C1.2 182.52,216.54 182.52,118.11 182.52,87.61 211.07,59.06 331.5,59.06 C12.2 C11.2 331.5,320.87 364.97,354.33 v2(643.11,354.33) U2.8
  Layer 1 w15: v2(717.91,354.33) v2(749.02,354.33)
  Bottom Layer w15: v2(780.51,312.99) 780.51,311.72 792.9,299.33 v3(792.9,160.19)
  Bottom Layer w20: v3(669,505) 669,397.34 v2(682.48,383.86)
  other v1: 265,121 265,167.32 1054.7,185.21 265,213.59 1054.7,259.65 265,261.97 544.3,307.67 585.83,307.67 369.29,334.65 410.87,334.65 444.84,334.65 544.3,340.09 585.83,340.09 1055.35,349.06 542.75,369.02 585.83,371.8 542.75,393.7 585.67,399.01 638.3,505 937,510.54 1253.65,522.86
  other v2: 749.02,312.99 812.01,312.99 643.11,324.8 682.48,324.8 717.91,324.8 682.48,354.33 780.51,354.33 812.01,354.33 643.11,383.86 717.91,383.86 749.02,395.67 780.51,395.67
IMON: R10.2 R12.2 U2.20 | length 168.9
  Top Layer w10: U2.20 890.07,383.86 890.25,383.67
  Top Layer w12: 890.25,383.67 913.67,407.08 R10.2 951.7,408.58 951.7,429.63 961,438.93 978.33,438.93 979.83,440.43 R12.2
L1: L1.1 R1.2 R2.2 R4.2 | length 951.6
  Top Layer w15: R4.2 v3(764.86,593.28)
  Top Layer w25: R2.2 R1.2 L1.1@288.68,521.65 ; L1.1@309.68,504.26 325.33,519.91 L1.1@325.33,523.94
  Layer 2 w15: v3(161,602.99) 161,626 193,658 746.33,658 764.86,639.47 v3(764.86,593.28)
MODE: R11.1 R13.2 U2.21 | length 192.4
  Top Layer w10: U2.21 880.54,403.54
  Top Layer w12: 880.54,403.54 952.61,475.61 R13.2 976.63,476.23 976.63,508.49 R11.1
NetC5_1: C5.1 D1.1 R5.2 U1.5 | length 689.7
  Top Layer w20: R5.2 715,653.84 740.16,679 1110,679 1129.11,659.89 1129.11,648.97 ; D1.1 1129.11,648.97 ; C5.1@1243.99,648.91 1129.11,648.97 ; C5.1@1251.83,640.6 1251.83,594.43 U1.5
NetC7_1: C7.1 U1.6 | length 219.6
  Top Layer w15: v3(1216.24,550.5) U1.6 ; v3(1314.67,538.98) 1316.07,540.38 1339.95,540.38 1351.15,551.58 C7.1
  Layer 2 w15: v3@1216.24,548.76 v3(1216.24,550.5) 1218.68,550.5 1238.68,570.51 1305.88,570.51 1312.95,563.44 1312.95,540.7 v3(1314.67,538.98)
NetC7_2: C7.2 U1.3 | length 62.3
  Top Layer w15: U1.3 1293.66,486.96 1348.54,486.96 C7.2
NetC10_1: C10.1 R10.1 | length 25.4
  Top Layer w15: R10.1 990.2,407.21 1015.35,407.21 C10.1
NetC16_2: C16.2 R17.2 | length 24.8
  Top Layer w12: C16.2 940.92,330.12 964.45,330.12 R17.2
PGOOD: U2.12
RT: C20.1 R18.2 U2.15 | length 76.5
  Top Layer w10: U2.15 840.55,280.39 842.36,278.58 R18.2 842.94,237.36 873.36,237.36 C20.1@873.93,237.93
SS: C19.2 U2.19 | length 83.5
  Top Layer w10: U2.19 847.52,364.25 920.6,364.25 C19.2@921.06,363.8
  Top Layer w12: C19.2@921.06,363.8 C19.2 C19.2
SW: L1.2 U2.7
SYNCIN: U2.13
SYNCOUT: R15.1 U2.14 | length 48.8
  Top Layer w10: R15.1 807.76,231.92 810.26,234.42 810.26,246.94 818.82,255.51 818.82,271.57 U2.14
UVLO: R6.1 R9.2 U2.3 | length 150.8
  Top Layer w6: U2.3 801.13,438.93 801.13,454.93 839.32,493.12 ; R6.1@830.48,523.1 834.98,527.6 R6.1@839.48,527.6
  Top Layer w10: 839.32,493.12 839.32,520.36 R6.1@837.46,522.22 ; R9.2@860.67,521.77 860.21,522.22 R6.1@837.46,522.22 ; R6.1@837.46,522.22 836.82,522.86 R6.1 833.78,522.22 R6.1@837.46,522.22
  Top Layer w15: R9.2@860.67,521.77 860.85,521.59 R9.2
VCC: C17.2 C18.1 U2.2 | length 125.1
  Top Layer w8: U2.2 819.82,437.93 819.82,452.58 829.9,462.66 833.54,462.66 867.46,496.59 C17.2 ; C17.2@867.61,498.41 C17.2 ; C17.2@873.31,500.46 C17.2 ; C18.1 894.83,504.73 886.69,496.59 C17.2
Vin: C1.1 C2.1 C3.1 R1.1 R2.1 R3.2 R6.2 R11.2 | length 1695.2
  Top Layer w15: R1.1 v3(91.93,602.99) ; R3.2 R3.2@803.12,564.34 ; v3(804.85,595) 803.12,593.28 R3.2@803.12,564.34 ; R6.2 828.64,562.86 827.16,564.34 R3.2@803.12,564.34 ; R11.2 1017.26,512 1030.71,512 1037.2,518.49 v3(1038.27,518.49)
  Top Layer w40: R1.1@95.56,525.28 R1.1 R2.1 91.93,374.02 107.64,358.31 C2.1 C3.1
  Layer 2 w15: v3(91.93,602.99) 174.13,685.19 758.65,685.19 804.85,639 v3(804.85,595) 1015,595 1038.27,571.73 v3(1038.27,518.49)
  Bottom Layer w15: v3@804,595 v3(804.85,595)
VOUT: C11.1 C12.1 C13.1 U2.9 | length 397.8
  Top Layer w40: C13.1 C12.1 C11.1 U2.9@669.29,263.78

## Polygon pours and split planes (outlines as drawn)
GND on Top Layer "TOP_LAYER_GND_P014" (solid, remove dead copper, pour order 14): 615.16,411.16 520.75,411.16 ccw(c520.75,387.42) 497.01,387.42 497.01,307.72 ccw(c508.48,307.72) 508.48,296.25 598.67,296.25 ccw(c598.67,312.74) 615.16,312.74
VOUT on Top Layer "TOP_LAYER_VOUT_P000" (solid, remove dead copper, pour order 0): 443.15,45.74 ccw(c448.89,45.74) 448.89,40 626.68,40 ccw(c626.68,56.43) 643.11,56.43 643.11,254.74 ccw(c628.8,254.74) 628.8,269.06 456.7,269.06 ccw(c456.7,255.51) 443.15,255.51
GND on Top Layer "TOP_LAYER_GND_P010" (solid, remove dead copper, pour order 10): 154.82,59.05 154.82,28.35 ccw(c169.17,28.35) 169.17,14 1366,14 ccw(c1366,26) 1378,26 1378,684 ccw(c1366,684) 1366,696 595.46,696 ccw(c595.46,679) 578.46,679 578.46,388.57 cw(c560.48,388.57) 560.48,370.59 381.23,370.59 ccw(c381.23,329.67) 340.3,329.67 cw(c279.69,329.67) 279.69,269.06 182.52,269.06 ccw(c182.52,243.61) 157.07,243.61 157.07,213.59
GND on Top Layer "TOP_LAYER_GND_P009" (solid, remove dead copper, pour order 9): 155.15,340.13 cw(c164.07,340.13) 164.07,349.06 627.94,349.06 cw(c627.94,348) 629,348 cw(c601.87,348) 601.87,320.87 437.68,320.87 ccw(c437.68,286.19) 403,286.19 403,50.42 cw(c385,50.42) 385,32.42 181.79,32.42 cw(c181.79,59.06) 155.15,59.06
SW on Top Layer "TOP_LAYER_SW_P007" (solid, remove dead copper, pour order 7): 430,421.84 430,644 cw(c446,644) 446,660 498,660 cw(c498,650) 508,650 508,555.98 ccw(c607.28,555.98) 607.28,456.69 709.32,456.69 cw(c709.32,444.88) 721.13,444.88 721.13,427.41 cw(c714.98,427.41) 714.98,421.26 446.67,421.26 cw(c446.67,438.93) 429,438.93
Vin on Top Layer "TOP_LAYER_VIN_P003" (solid, remove dead copper, pour order 3): 11,676 cw(c24,676) 24,689 100,689 cw(c100,670) 119,670 119,40 cw(c93,40) 93,14 37,14 cw(c37,40) 11,40
L1 on Top Layer "TOP_LAYER_L1_P001" (solid, remove dead copper, pour order 1): 151,658 151,390 ccw(c165,390) 165,376 301,376 ccw(c301,415) 340,415 340,664.9 ccw(c325.33,664.9) 325.33,679.57 167.57,679.57 ccw(c167.57,662) 150,662
GND on Layer 1 "LAYER_1_GND_P011" (solid, remove dead copper, pour order 11): 11,674 cw(c27,674) 27,690 1360,690 cw(c1360,672) 1378,672 1378,30 cw(c1363,30) 1363,15 36,15 cw(c36,40) 11,40
GND on Layer 2 "LAYER_2_GND_P012" (solid, remove dead copper, pour order 12): 11,639 11,670 cw(c31,670) 31,690 1363,690 cw(c1363,675) 1378,675 1378,31 cw(c1359,31) 1359,12 39,12 cw(c39,40) 11,40 11,110 cw(c12,110) 12,111
GND on Bottom Layer "BOTTOM_LAYER_GND_P013" (solid, remove dead copper, pour order 13): 65,14 37,14 cw(c37,40) 11,40 11,663 cw(c38,663) 38,690 1359,690 cw(c1359,671) 1378,671 1378,38 cw(c1351,38) 1351,11

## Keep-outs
Keep-Out Layer:
  text ".Layer_Name" at 577,-858.49 h60

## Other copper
Top Layer:
  text ".Layer_Name" at 577,-858.49 h60
Bottom Layer:
  text ".Layer_Name" at 577,-858.49 h60

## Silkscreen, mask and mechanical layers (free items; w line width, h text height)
Top Overlay:
  text "PMP31404_RevA" at 955.09,40 h30
  text ".Layer_Name" at 577,-858.49 h15
Bottom Overlay:
  text ".Layer_Name" at 577,-858.49 h60
Top Paste:
  text ".Layer_Name" at 577,-858.49 h60
Bottom Paste:
  text ".Layer_Name" at 577,-858.49 h60
Top Solder:
  text ".Layer_Name" at 577,-858.49 h60
  text ".Layer_Name" at 577,-858.49 h60
Bottom Solder:
  text ".Layer_Name" at 577,-858.49 h60
Drill Guide:
  text ".Layer_Name" at 577,-858.49 h60
M1 Board Outline:
  the board outline again, w10
  text ".Layer_Name" at 577,-858.49 h60
M2 Board Dimensions:
  rectangle: 125,-400 500,-275
  rectangle: 0,-275 125,-150
  lines w7: 0,-275 1000,-275 ; 125,-400 125,-150 ; 250,-400 250,-150 ; 500,-400 500,-150 ; 750,-400 750,-150 ; 0,-400 0,-150 1000,-150 1000,-400 0,-400
  text ".Layer_Name" at 577,-858.49 h60
M3 3D STEP Top:
  text ".Layer_Name" at 577,-858.49 h60
M4 3D STEP Bottom:
  text ".Layer_Name" at 577,-858.49 h60
M5 Assembly Top:
  lines w10: -292,-930.17 6308,-930.17 ; -292,-726.83 6310,-726.83 ; -292,-523.5 -292,-1133.5 3713,-1133.5 6310,-1133.5 6310,-523.5 -291.5,-523.5 -291.5,-1133.5 1284,-1133.5 ; 2173,-1133.5 2173,-523.5 ; 3440,-726.83 3440,-523.5 ; 4280,-726.83 4280,-523.5 ; 4902,-1140 4902,-937.17
  text "COMPONENTS MARKED 'DNP' SHOULD NOT BE POPULATED." at 1153.5,-318.5 h60
  text "ASSEMBLY VARIANT:" at 1153,-434 h60
  text ".VariantName" at 2189,-434 h60
  text "PCB VIEWED FROM TOP SIDE" at -228.5,-655.67 h60
  text "BOARD #:" at 2248,-655.67 h60
  text ".PRJ_Number" at 2793.5,-655.67 h60
  text "REV:" at 3638,-655.67 h60
  text ".PCB_Rev" at 3929.5,-655.67 h60
  text "SVN REV:" at 4476,-655.67 h60
  text ".VersionControl_RevNumber" at 4982,-655.67 h60
  text "PLOT NAME =" at -228.5,-1064.34 h60
  text ".plot_File_Name" at 577,-1064.34 h60
  text "GENERATED    :" at 2250,-1064.34 h60
  text ".Print_Date" at 3119.5,-1064.34 h60
  text ".Print_Time" at 3848.5,-1064.34 h60
  text "TEXAS INSTRUMENTS" at 5113,-1064.34 h60
M6 Assembly Bottom:
  lines w10: -292.5,-727.33 6309.5,-727.33 ; -290.5,-930.67 6309.5,-930.67 ; 1115.5,-1140.5 1115.5,-937.67 ; 1737.5,-727.33 1737.5,-524 ; 2577.5,-727.33 2577.5,-524 ; 3844.5,-1134 3844.5,-524 ; 4733.5,-1134 6309,-1134 6309,-524 -292.5,-524 -292.5,-1134 2304.5,-1134 6309.5,-1134 6309.5,-524
  text "COMPONENTS MARKED 'DNP' SHOULD NOT BE POPULATED." at 6102,-318 h60
  text ".VariantName" at 5058,-434 h60
  text "ASSEMBLY VARIANT:" at 6097,-434 h60
  text ".VersionControl_RevNumber" at 1035.5,-656.17 h60
  text "SVN REV:" at 1541.5,-656.17 h60
  text ".PCB_Rev" at 2088,-656.17 h60
  text "REV:" at 2379.5,-656.17 h60
  text ".PRJ_Number" at 3224,-656.17 h60
  text "BOARD #:" at 3769.5,-656.17 h60
  text "PCB VIEWED FROM BOTTOM SIDE" at 6246,-656.17 h60
  text "TEXAS INSTRUMENTS" at 904.5,-1064.84 h60
  text ".Print_Time" at 2169,-1064.84 h60
  text ".Print_Date" at 2898,-1064.84 h60
  text "GENERATED    :" at 3767.5,-1064.84 h60
  text ".plot_File_Name" at 5440.5,-1064.84 h60
  text "PLOT NAME =" at 6246,-1064.84 h60
M9 Title Sheet:
  drawing of 63 lines, arcs and shapes, not listed
  text "1" at 1389.5,18376 h70
  text "2" at 5384.5,18376 h70
  text "3" at 9379.5,18376 h70
  text "4" at 13380.51,18376 h70
  text "5" at 17378.84,18376 h70
  text "6" at 21377.18,18376 h70
  text "7" at 25378.84,18376 h70
  text "8" at 29373.84,18376 h70
  text "A" at -467.5,15978 h70
  text "A" at 31232.5,15978 h70
  text "B" at -467.5,10978 h70
  text "B" at 31232.5,10978 h70
  text "C" at -467.5,5978 h70
  text "C" at 31232.5,5978 h70
  text "D" at -467.5,978 h70
  text "D" at 31232.5,978 h70
  text "PROJECT TITLE:" at 28147.5,268.61 h45
  text ".PRJ_Title" at 28197.5,135.28 h70
  text "DESIGNED FOR:" at 28147.5,-32.39 h45
  text ".PRJ_Customer" at 28197.5,-172.39 h70
  text "FILE NAME:" at 28147.5,-332.39 h45
  text ".PCB_File_Name_No_Path" at 28197.5,-452.39 h70
  text "Texas Instruments (TI) and/or its licensors do not warrant the accuracy or completeness of this specification" at 23178,-614.23 h45
  text "ENGINEER:" at 28147.5,-622.39 h45
  text "LAYOUT BY:" at 29652.5,-622.39 h45
  text "or any information contained therein. TI and/or its licensors do not warrant that this design will meet" at 23133.01,-726.89 h45
  text ".PRJ_Engineer" at 28197.5,-777.38 h70
  text ".PCB_Layout" at 29703,-777.38 h70
  text "the specifications, will be suitable for your application or fit for any particular purpose, or will operate in" at 23133.01,-839.56 h45
  text ".Layer_Name" at 577,-858.49 h60
  text "ALTIUM DESIGNER VERSION:" at 29652.5,-932.39 h45
  text "an implementation. TI and/or its licensors do not warrant that the design is production worthy. You should" at 23133.01,-952.22 h45
  text "completely validate and test your design implementation to confirm the system functionality for your application." at 23178,-1064.89 h45
  text ".print_Scale" at 28197.5,-1065.72 h70
  text ".Application_BuildNumber" at 29703,-1065.72 h70
  text "1" at 1389.5,-1319 h70
  text "2" at 5384.5,-1319 h70
  text "3" at 9379.5,-1319 h70
  text "4" at 13380.51,-1319 h70
  text "5" at 17378.84,-1319 h70
  text "6" at 21377.18,-1319 h70
  text "7" at 25378.84,-1319 h70
  text "8" at 29373.84,-1319 h70
M10 Fab Notes:
  drawing of 189 lines, arcs and shapes, not listed
  text "DESIGN INFORMATION" at 29188.02,6365.17 h60
  text "MIN. TRACK WIDTH:" at 28543.46,6233.05 h60
  text "8" at 29639.7,6233.05 h60
  text "MIL" at 29794.46,6233.05 h60
  text "MIN. CLEARANCE:" at 28543.46,6108.92 h60
  text "7.874" at 29468.5,6108.92 h60
  text "MIL" at 29794.46,6108.92 h60
  text "MIN. VIA PAD SIZE:" at 28543.46,5984.8 h60
  text "24" at 29609.71,5984.8 h60
  text "MIL" at 29794.46,5984.8 h60
  text "0.05mm (2MIL)" at 29238.46,5854.9 h60
  text "MINIMUM ANNULAR RING" at 28214.23,5846.67 h60
  text "EXTERNAL" at 29946.46,5846.67 h60
  text "PER" at 28414.23,5736.55 h60
  text "IPC-D-275 CLASS 2 LEVEL C" at 28634.23,5736.54 h60
  text "MIL, HOLES" at 30122.46,5636.07 h60
  text "+/-" at 29730,5627.48 h60
  text "+/-" at 30584,5627.48 h60
  text "REGISTRATION TOLERANCES:" at 28214.23,5626.42 h60
  text "METAL" at 29414,5626.42 h60
  text "5" at 29990.2,5626.42 h60
  text "3" at 30823.2,5626.42 h60
  text "MIL" at 30939.46,5626.42 h60
  text "HOLE SIZE TOLERANCE (UNLESS OTHERWISE SPECIFIED):" at 28214.23,5528.1 h60
  text "+/-" at 30584,5525.23 h60
  text "3" at 30823.2,5524.17 h60
  text "MIL" at 30939.46,5524.17 h60
  text "MATERIAL:" at 28139.46,5386.52 h60
  text "FR-4 High Tg" at 29125.9,5258 h60
  text "X" at 28981.46,5250.01 h60
  text "FR-4" at 28560.46,5245.49 h60
  text "OTHER" at 30048.46,5245.49 h60
  text "62 MIL (1.6mm) +/-10%" at 28880.56,5102.46 h60
  text "X" at 28760.46,5100.01 h60
  text "THICKNESS:" at 28214.23,5094.24 h60
  text "OTHER" at 30165.46,5094.24 h60
  text "TOLERANCE:" at 28214.23,4955.92 h60
  text "X" at 29062.46,4955.92 h60
  text "ANSI IPC-6012 TYPE 3 CLASS 2" at 29240.48,4955.92 h60
  text "OTHER +/-" at 29240.46,4811.73 h60
  text "BOW & TWIST:" at 28214.23,4666.54 h60
  text "X" at 29062.46,4666.54 h60
  text "ANSI IPC-6012 TYPE 3 CLASS 2" at 29240.48,4666.54 h60
  text "OTHER +/-" at 29240.46,4519.85 h60
  text "DRILLING:" at 28139.46,4389.23 h60
  text "NC_DRILL FILES" at 29900.46,4284.04 h60
  text "REFERENCE:" at 28214.23,4280.1 h60
  text "X" at 28871.46,4280.01 h60
  text "AS SHOWN" at 29049.46,4280.1 h60
  text "X" at 29772.46,4280.1 h60
  text "OTHER" at 30198.46,4137.85 h60
  text "PTH COPPER THICKNESS:" at 28213.91,4134.32 h60
  text "X" at 29353.14,4134.32 h60
  text "20-30 um" at 29481.14,4134.32 h60
  text "BOARD FINISH:" at 28139.46,3986.73 h60
  text "SILKSCREEN:" at 28294.68,3876.6 h60
  text "X" at 29252.46,3876.6 h60
  text "TOP" at 29369.46,3876.6 h60
  text "X" at 29762.46,3876.6 h60
  text "BOTTOM" at 29880.46,3876.6 h60
  text "SILKSCREEN COLOR:" at 28294.68,3721.41 h60
  text "X" at 29251.46,3721.41 h60
  text "WHITE" at 29369.46,3721.41 h60
  text "OTHER" at 29880.46,3721.41 h60
  text "X" at 29382.46,3577.96 h60
  text "GREEN" at 29500.46,3577.96 h60
  text "OTHER" at 30118.46,3577.96 h60
  text "SOLDER RESIST COLOR:" at 28294.68,3571.1 h60
  text "X" at 29382.46,3423.71 h60
  text "MATTE" at 29500.46,3423.71 h60
  text "SEMI-GLOSS" at 30118,3423.07 h60
  text "IMMERSION GOLD (ENIG)" at 29200.46,3250.94 h60
  text "ENEPIG" at 30538,3243.72 h60
  text "SURFACE FINISH:" at 28139.46,3242.72 h60
  text "X" at 29022.46,3242.72 h60
  text "IMM. TIN/SILVER OR EQUIV" at 28469,3105.4 h60
  text "OTHER" at 29900.46,3101.47 h60
  text "ARRAY/PANEL:" at 28139.46,2946.09 h60
  text "CUT AND TRIM PER M1 BOARD OUTLINE" at 29200.46,2937.87 h60
  text "N.C. ROUTE" at 29200.46,2801.9 h60
  text "X" at 29888.46,2801.9 h60
  text "V. SCORE" at 30066.46,2801.9 h60
  text "CERTIFICATION:" at 28139.46,2672.77 h60
  text "MATERIALS AND WORKMANSHIP FOR ALL PCBS" at 28864.46,2672.77 h60
  text "TO MEET OR EXCEED THE REQUIREMENTS OF:" at 28864.46,2578.71 h60
  text "X" at 28501.97,2450.08 h60
  text "ANSI IPC-A-600F CLASS ->" at 28629.96,2450.08 h60
  text "X" at 30277.97,2450.08 h60
  text "2" at 30387.96,2450.08 h60
  text "1" at 30072.96,2448.58 h60
  text "3" at 30741.96,2448.58 h60
  text "X" at 29313.97,2302.39 h60
  text "RoHS" at 29441.96,2302.39 h60
  text "OTHER" at 30086.36,2302.39 h60
  text "PER ORDER" at 30483.42,2302.39 h60
  text "ALL BOARDS MUST MEET OR EXCEED UL94-V0 REQUIREMENTS." at 28167,2148.57 h60
  text "PCB MUST BEAR THE UL94V-0 UL REGISTERED MATERIAL ID NUMBER" at 28167,2032.5 h60
  text "ADDITIONAL REQUIREMENTS:" at 28139.46,1863.08 h60
  text "MICROSECTION:" at 28214.23,1755.95 h60
  text "YES" at 29119.96,1755.95 h60
  text "REQUIRED" at 29981.46,1611.62 h60
  text "BARE BOARD ELEC. TEST:" at 28214.23,1608.76 h60
  text "NONE" at 29519.96,1608.76 h60
  text "X" at 29863.46,1608.76 h60
  text "PER ORDER" at 30573.46,1608.76 h60
  text "XX MIL VIAS REQUIRE NON-CONDUCTIVE FILL AND PLANARIZE" at 28382.38,1403.82 h59
  text "XX MIL VIAS REQUIRE CONDUCTIVE FILL AND PLANARIZE" at 28390.38,1299.84 h60
  text "OUTER XX MIL TRACES REQUIRE 50 OHM SINGLE-ENDED IMPEDANCE" at 28389.39,1136.46 h58
  text "LAYER 2 & 3 (INNER LAYERS) XX MIL WIDE, XX MIL SPACE / TRACES REQUIRE 100 OHM DIFFERENTIAL IMPEDANCE" at 28381.39,900.74 h60
  text ".Layer_Name" at 577,-858.49 h60
M11 Gerber Information:
  lines w10: -292,-930.17 6308,-930.17 ; -292,-726.83 6310,-726.83 ; -292,-523.5 -292,-1133.5 3713,-1133.5 6310,-1133.5 6310,-523.5 -291.5,-523.5 -291.5,-1133.5 1284,-1133.5 ; 2173,-1133.5 2173,-523.5 ; 3440,-726.83 3440,-523.5 ; 4280,-726.83 4280,-523.5 ; 4902,-1140 4902,-937.17
  text "ALL ARTWORK VIEWED FROM TOP SIDE" at -228.5,-655.67 h60
  text "BOARD #:" at 2248,-655.67 h60
  text ".PRJ_Number" at 2793.5,-655.67 h60
  text "REV:" at 3638,-655.67 h60
  text ".PCB_Rev" at 3929.5,-655.67 h60
  text "SVN REV:" at 4476,-655.67 h60
  text ".VersionControl_RevNumber" at 4982,-655.67 h60
  text "LAYER NAME =" at -228.5,-858.49 h60
  text "PLOT NAME =" at -228.5,-1064.34 h60
  text ".plot_File_Name" at 577,-1064.34 h60
  text "GENERATED    :" at 2250,-1064.34 h60
  text ".Print_Date" at 3119.5,-1064.34 h60
  text ".Print_Time" at 3848.5,-1064.34 h60
  text "TEXAS INSTRUMENTS" at 5113,-1064.34 h60
M12 Stackup:
  drawing of 295 lines, arcs and shapes, not listed
  text "Layer" at 26553.88,18012.74 h60
  text "Name" at 26963.79,18012.74 h60
  text "Material" at 27893.54,18012.74 h60
  text "Thickness" at 28753.3,18012.74 h60
  text "Constant" at 29403.14,18012.74 h60
  text "Board Layer Stack" at 29973,18012.74 h60
  text "Top Overlay" at 26963.79,17892.74 h60
  text "Top Solder" at 26963.79,17772.74 h60
  text "Solder Resist" at 27893.54,17772.74 h60
  text "0.40mil" at 28753.3,17772.74 h60
  text "3.5" at 29403.14,17772.74 h60
  text "1" at 26553.88,17652.74 h60
  text "Top Layer" at 26963.79,17652.74 h60
  text "4.13mil" at 28753.3,17652.74 h60
  text "Dielectric 1" at 26963.79,17532.74 h60
  text "PP-006" at 27893.54,17532.74 h60
  text "2.80mil" at 28753.3,17532.74 h60
  text "4.1" at 29403.14,17532.74 h60
  text "2" at 26553.88,17412.74 h60
  text "Layer 1" at 26963.79,17412.74 h60
  text "CF-004" at 27893.54,17412.74 h60
  text "2.76mil" at 28753.3,17412.74 h60
  text "Dielectric1" at 26963.79,17292.74 h60
  text "FR-4 High Tg" at 27893.54,17292.74 h60
  text "59.20mil" at 28753.3,17292.74 h60
  text "4.8" at 29403.14,17292.74 h60
  text "3" at 26553.88,17172.74 h60
  text "Layer 2" at 26963.79,17172.74 h60
  text "CF-004" at 27893.54,17172.74 h60
  text "2.76mil" at 28753.3,17172.74 h60
  text "Dielectric 2" at 26963.79,17052.74 h60
  text "PP-006" at 27893.54,17052.74 h60
  text "2.80mil" at 28753.3,17052.74 h60
  text "4.1" at 29403.14,17052.74 h60
  text "4" at 26553.88,16932.74 h60
  text "Bottom Layer" at 26963.79,16932.74 h60
  text "4.13mil" at 28753.3,16932.74 h60
  text "Bottom Solder" at 26963.79,16812.74 h60
  text "Solder Resist" at 27893.54,16812.74 h60
  text "0.40mil" at 28753.3,16812.74 h60
  text "3.5" at 29403.14,16812.74 h60
  text "Bottom Overlay" at 26963.79,16692.74 h60
  text ".Layer_Name" at 577,-858.49 h60
M13 Component Bodies Top:
  text ".Layer_Name" at 577,-858.49 h60
M14 Component Bodies Bottom:
  text ".Layer_Name" at 577,-858.49 h60
M15 Courtyards Top:
  text ".Layer_Name" at 577,-858.49 h60
M16 Courtyards Bottom:
  text ".Layer_Name" at 577,-858.49 h60
Drill Drawing:
  text ".Layer_Name" at 577,-858.49 h60
M17 Embedded Cavity:
  text ".Layer_Name" at 577,-858.49 h60
M18 Embedded Assembly:
  text ".Layer_Name" at 577,-858.49 h60
M19 Embedded Keepout:
  text ".Layer_Name" at 587,-848.49 h60

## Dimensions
0,0 to 0,708.66 on M2 Board Dimensions
0,0 to 1387.8,0 on M2 Board Dimensions
0,-400 to 1000,-400 on M2 Board Dimensions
